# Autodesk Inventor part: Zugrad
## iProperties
Created: 2007-03
Part Number: Zugrad
Document SubType Name: Modeling
Designer: Benno
Manufacturer: Standard
Standards Organization: Custom
Author: Benno
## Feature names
1. Extrusion1
2. Extrusion2
3. Extrusion3
4. Bohrung1 [Hole]
